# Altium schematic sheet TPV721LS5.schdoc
size 127 x 101 mm
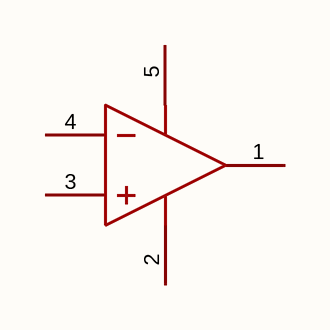
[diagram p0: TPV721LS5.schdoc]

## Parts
U?  tpv721ls5  [SOT-23-5_L3.0-W1.5-P0.95-LS2.8-BL]  (value not drawn)

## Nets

Not connected (* = marked no-connect by the designer): U? 1(OUT) 2(V-) 3(IN+) 4(IN-) 5(V+)

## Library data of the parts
U? = tpv721ls5: 放大器数:1;轨到轨:轨到轨输入,轨到轨输出;增益带宽积(GBW):8MHz;输入失调电压(Vos):2.5mV;压摆率(SR):6V/us;输入偏置电流(Ib):10pA;; Manufacturer: TECH PUBLIC(台舟); AddInBom: yes; ModelId: 424d41c645fb4cc2a3598f66fad27964; ModelTransform: 118.11,110.236,0,0,0,0,0,0,0; Number of Channels: 1; Gain Bandwidth Product: 8MHz; Vos - Input Offset Voltage: 2.5mV; Input Offset Voltage Drift(Vos TC): 600nV/℃; Slew Rate: 6V/us; Ib - Input Bias Current: 10pA; Input Offset Current(Ios): 5pA; Input Voltage Noise Density: 8nV/√Hz@1kHz; Common Mode Rejection Ratio(CMRR): 95dB; Quiescent Current: 510uA; Output Current: 26mA; Single supply: 2.2V~5.5V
